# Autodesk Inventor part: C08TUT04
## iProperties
Created: 2009-04
Part Number: C08TUT04
Document SubType Name: Modeling
Designer: Sham
Density: 1 g/cm^3
Author: Sham
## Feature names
1. Extrusion1
2. Extrusion2
3. Extrusion3
4. Extrusion4
5. FaceDraft1
6. Fillet1
